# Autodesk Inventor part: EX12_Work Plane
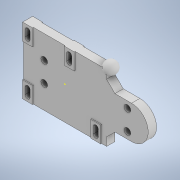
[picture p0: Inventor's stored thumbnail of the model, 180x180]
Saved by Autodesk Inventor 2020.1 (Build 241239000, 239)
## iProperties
Created: 2019-10
Part Number: EX12_Work Plane
Material: Generic
Document SubType Name: Modeling
Designer: Synergysoft Dell02
Density: 1 g/cm^3
Appearance: Default
Author: Synergysoft Dell02
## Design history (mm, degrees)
sketch "Sketch1"
  geometry: L1 (-50, -40)-(-50, 40); L2 (-50, 40)-(50, 40); L3 (50, 40)-(50, 30); L4 (50, 30)-(60, 20); L5 (60, 20)-(100, 20); L6 (100, 20)-(100, -20); L7 (100, -20)-(60, -20); L8 (60, -20)-(50, -30); L9 (50, -30)-(50, -40); L10 (50, -40)-(-50, -40); L11 (-50, 0)-(100, 0); L12 (-50, 40)-(-38, 40); L13 (-38, 40)-(-38, 20); L14 (-38, 20)-(-50, 20); L15 (-50, 20)-(-50, 40); L16 (-44, 34)-(-44, 26); L17 (-47, 34)-(-47, 26); L18 (-41, 26)-(-41, 34); L19 (12, 20)-(0, 20); L20 (6, 34)-(6, 26); L21 (3, 34)-(3, 26); L22 (9, 26)-(9, 34); L23 (12, 40)-(12, 20); L24 (0, 20)-(0, 40); L25 (0, 40)-(12, 40); L26 (-38, -40)-(-50, -40); L27 (-44, -26)-(-44, -34); L28 (-47, -26)-(-47, -34); L29 (-41, -34)-(-41, -26); L30 (-38, -20)-(-38, -40); L31 (-50, -40)-(-50, -20); L32 (-50, -20)-(-38, -20); L33 (44, -40)-(38.869, -40); L34 (38, -26)-(38, -34); L35 (35, -26)-(35, -34); L36 (41, -34)-(41, -26); L37 (44, -20)-(44, -40); L38 (32, -40)-(32, -20); L39 (32, -20)-(44, -20); C1 r 4 at (75, 12); C2 r 4 at (75, -12); C3 r 4 at (-25, 12); C4 r 4 at (-25, -12); A1 r 3 centre (-44, 34) between (-41, 34) and (-47, 34); A2 r 3 centre (-44, 26) between (-47, 26) and (-41, 26); A3 r 3 centre (6, 26) between (3, 26) and (9, 26); A4 r 3 centre (6, 34) between (9, 34) and (3, 34); A5 r 3 centre (-44, -34) between (-47, -34) and (-41, -34); A6 r 3 centre (-44, -26) between (-41, -26) and (-47, -26); A7 r 3 centre (38, -34) between (35, -34) and (41, -34); A8 r 3 centre (38, -26) between (41, -26) and (35, -26); 23 further points
  constraints: 86 end point, 16 point on circle, 16 tangent, 15 midpoint, 13 parallel, 12 centre point, 9 perpendicular, 6 horizontal, 6 horizontal alignment, 6 vertical, 5 point on line, 5 vertical alignment, 7 other
  dimensions: "d1" = 100 distance of L9.end L1.start; "d2" = 80 distance of L1.start L1.end; "d3" = 40 distance of L5.end L6.end; "d4" = 135 deg angle of L5 L4; "d6" = 100 distance from line of L6 point (0, 0); "d7" = 10 distance from line of L2 L3.end; "d10" = 12 distance of L13.end L14.end; "d11" = 20 distance of L12.end L13.end; "d12" = 8 distance of L16.start L16.end; "d13" = 3 radius of A2; "d14" = 12 distance of L19.start L19.end; "d15" = 20 distance of L23.start L19.start; "d16" = 8 distance of L20.start L20.end; "d17" = 3 radius of A3; "d18" = 12 distance of L26.start L26.end; "d19" = 20 distance of L30.start L26.start; "d20" = 8 distance of L27.start L27.end; "d21" = 3 radius of A5; "d23" = 20 distance of L37.start L33.start; "d24" = 8 distance of L34.start L34.end; "d25" = 3 radius of A7; "d26" = 6 distance from line of L20 point (0, 0); "d27" = 6 distance between parallel lines of L1 L27; "d31" = 12 distance between parallel lines of L37 L38; "d32" = 12 distance between parallel lines of L9 L34; "d37" = 8 diameter of C1; "d38" = 25 distance from line of L6 C1.centre; "d39" = 8 distance from line of L5 C1.centre; "d42" = 24 distance of C1.centre C2.centre; "d45" = 100 distance of C1.centre C3.centre
extrude "Extrusion1" new body sketch "Sketch1" stored distance "d8" = 10; taper "d9" = 0 deg
extrude "Extrusion3" join sketch "Sketch1" stored distance "d33" = 12; taper "d34" = 0 deg
extrude "Extrusion4" cut sketch "Sketch1" stored distance "d35" = 12; taper "d36" = 0 deg
sketch "Sketch2"
  geometry: 1 further point
extrude "Extrusion5" cut sketch "Sketch1" stored distance "d48" = 10; taper "d49" = 0 deg
workplane "Work Plane1"
fillet "Fillet1"
sketch "Sketch3"
  geometry: L1 (50, 47.5)-(50, 32.5); A1 r 7.5 centre (50, 40) between (50, 47.5) and (50, 32.5); 3 further points
  constraints: 2 coincident, 2 end point, 2 point on circle, 1 centre point, 1 midpoint, 1 vertical
  dimensions: "d51" = 15 diameter of A1
revolve "Revolution1" sketch "Sketch3" stored, may be unused: angle "d52" = 90 deg
body "Solid1"
